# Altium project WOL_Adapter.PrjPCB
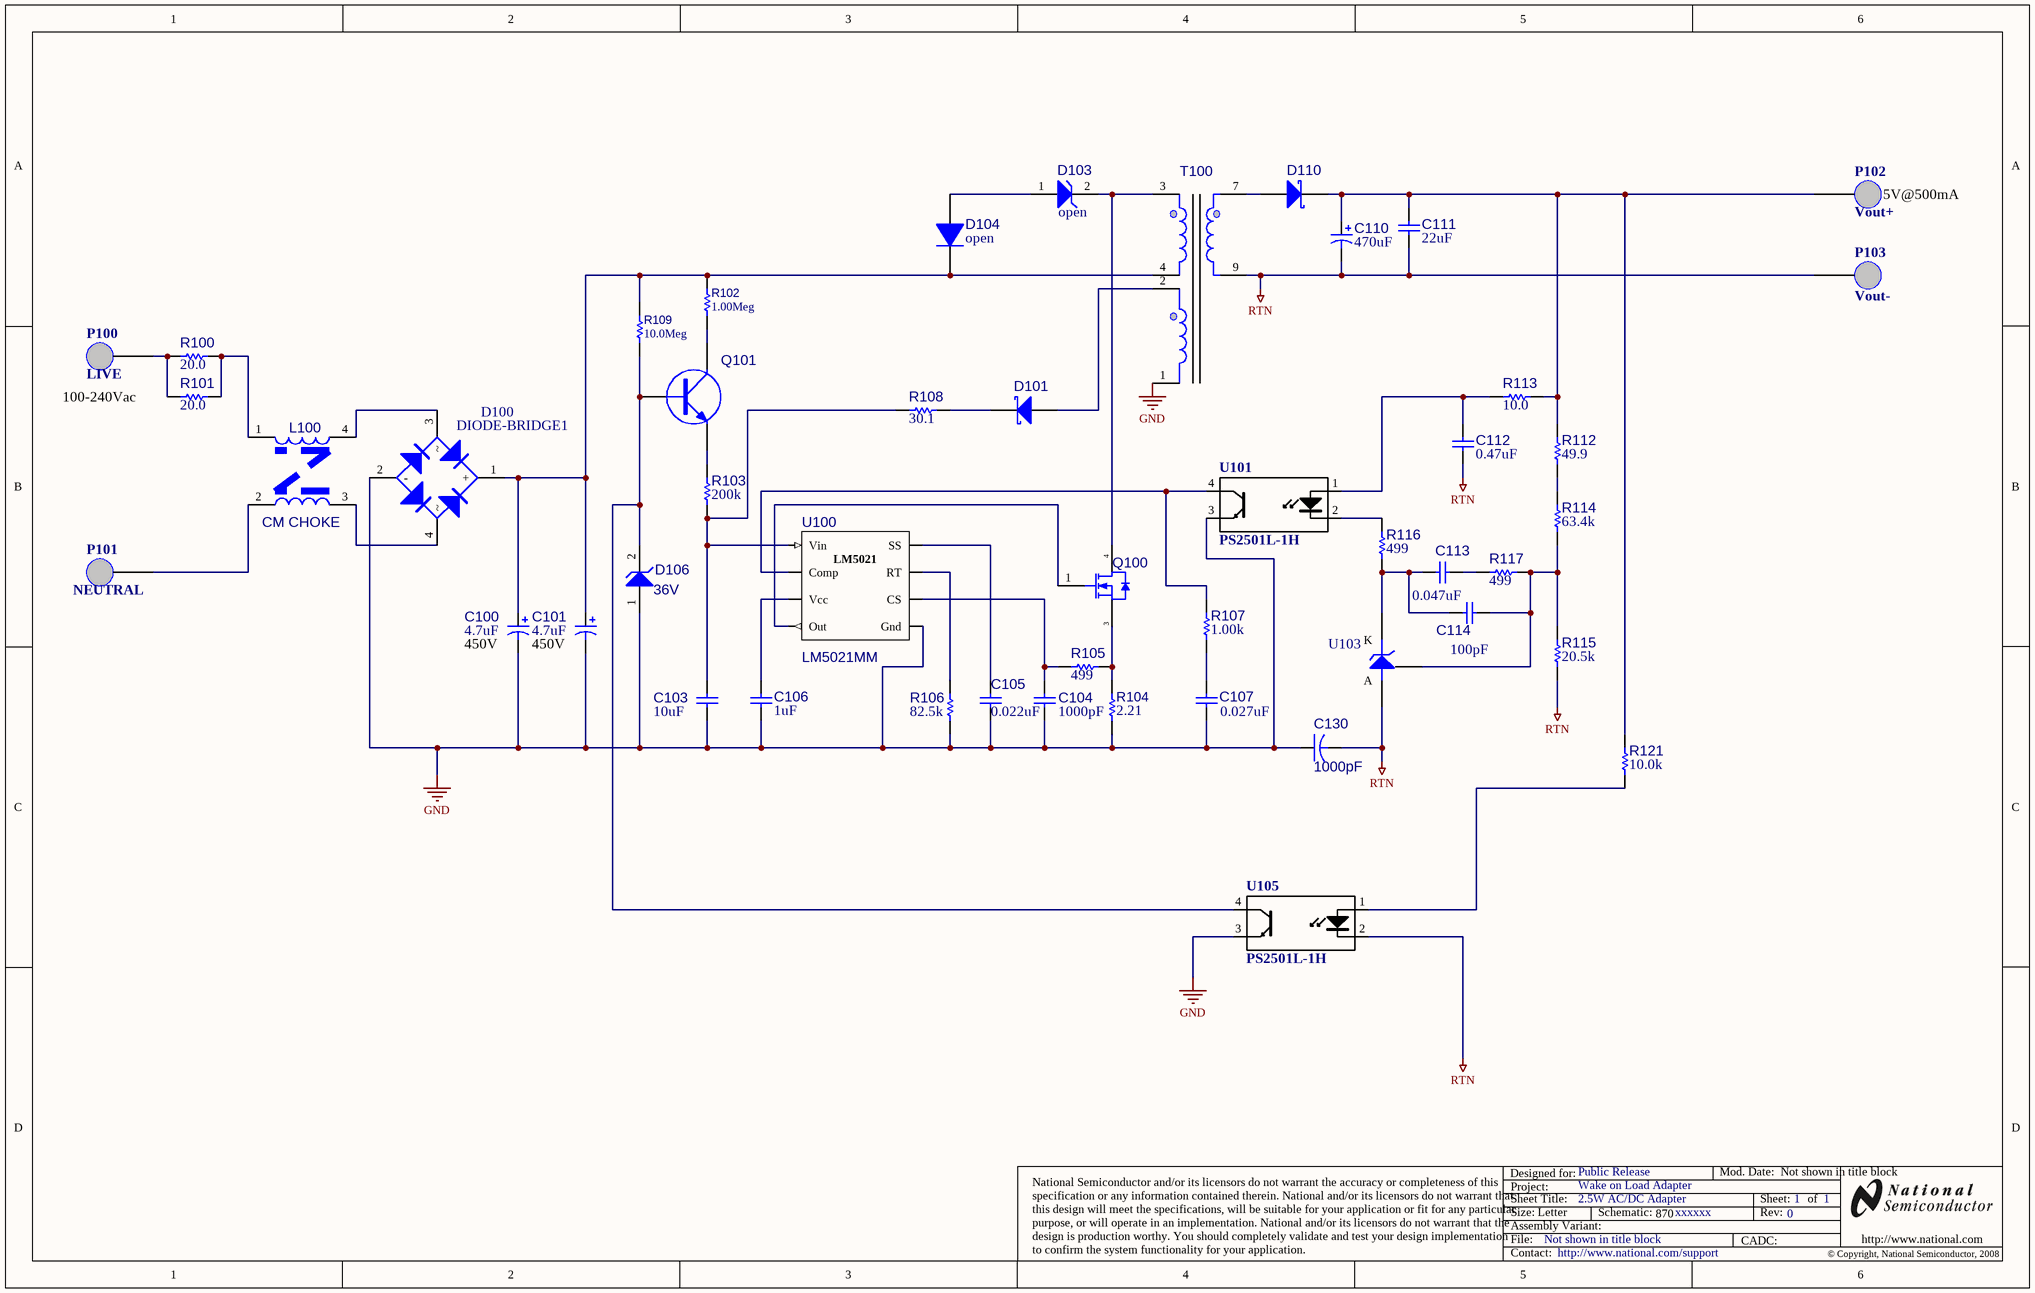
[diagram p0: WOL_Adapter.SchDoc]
PCB_MinorRev: -001; PRJ_BasePN: xxxxxx; PRJ_Customer: Public Release; PRJ_Title: Wake on Load Adapter; SCH_Rev: 0; SCH_SheetTotal: 1; TechSupport: http://www.national.com/support
1 sheet, 48 parts. Net scope: global (net labels, ports and power ports of the same name join across sheets).
Board file: WOL_Adapter.PcbDoc

## Sheet WOL_Adapter.SchDoc: 2.5W AC/DC Adapter
size B; Date: Not shown in title block; ApprovedBy: Not shown in title block; CheckedBy: Not shown in title block; Author: Not shown in title block; CompanyName: Not shown in title block; DrawnBy: Not shown in title block; Engineer: Not shown in title block; Organization: Not shown in title block; Address1: Not shown in title block; Address2: Not shown in title block; Address3: Not shown in title block; Address4: Not shown in title block; DocumentNumber: Not shown in title block; Revision: Use project parameter SCH_Rev; SheetNumber: 1; SheetTotal: Use project parameter SCH_SheetTotal; PageSetup: Record=PageOptions|CenterHorizontal=True|CenterVertical=True|PrintScale=1.09|XCorrection=1.00|YCorrection=1.00|PrintKind=0|BorderSize=5000000|LeftOffset=0|BottomOffset=0|Orientation=2|PaperLength=1000|PaperWidth=1000|Scale=100|PaperSource=15|PrintQuality=600|MediaType=1|DitherType=10|PaperKind=11x17|PrintScaleMode=1

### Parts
C100  value 4.7uF  VDC_V: 450V  [10mm th cap]  (hidden comment: UVR2W4R7MPD)
C101  value 4.7uF  VDC_V: 450V  [10mm th cap]  (hidden comment: UVR2W4R7MPD)
C103  value 10uF  [1210]  (hidden comment: C3225X7R1E106M)
C104  value 1000pF  [0805]  (hidden comment: C2012X7R1H102K)
C105  value 0.022uF  [0805]  (hidden comment: C2012X7R2A223K)
C106  value 1uF  [0805]  (hidden comment: C2012X5R1E105K)
C107  value 0.027uF  [0805]  (hidden comment: CC0805KRX7R9BB273)
C110  value 470uF  [SM_RADIAL_F]  (hidden comment: EEV-FK0J471P)
C111  value 22uF  [0805]  (hidden comment: C2012X5R0J226M)
C112  value 0.47uF  [0805]  (hidden comment: C2012X7R1E474K)
C113  value 0.047uF  [0805]  (hidden comment: GRM21BR71H473KA01L)
C114  value 100pF  [0805]  (hidden comment: GQM2195C1H101JB01D)
C130  1000pF  [1808]
D100  DIODE-BRIDGE1  [bridge]
D101  1N4148W-7-F  [SOD-123]  (value not drawn)
D103  Vaule: open  [SMA]  (hidden comment: CMZ5938B)
D104  value open  [SMA]  (hidden comment: 10MQ100NTRPBF)
D106  36V  [SMA]
D110  B2100-13  [SMB]  (value not drawn)
L100  CM CHOKE  [BU9S]
P100  LIVE  [PAD175]
P101  NEUTRAL  [PAD175]
P102  Vout+  [PAD175]
P103  Vout-  [PAD175]
Q100  SPD06N80C3  [DPAK]  (value not drawn)
Q101  (no value)  [sot-23]
R100  value 20.0  [1206]  (hidden comment: CRCW1206-20R0FRT1)
R101  value 20.0  [1206]  (hidden comment: CRCW1206-20R0FRT1)
R102  value 1.00Meg  [0805]  (hidden comment: KTR10EZPJ105)
R103  value 200k  [0805]  (hidden comment: CRCW0805200kFKEA)
R104  value 2.21  [0805]  (hidden comment: CRCW08052R21FNEA)
R105  value 499  [0805]  (hidden comment: CRCW0805499RFKEA)
R106  value 82.5k  [0805]  (hidden comment: CRCW080582k5FKEA)
R107  value 1.00k  [0805]  (hidden comment: CRCW08051k00FKEA)
R108  value 30.1  [0805]  (hidden comment: CRCW080530R1FKEA)
R109  value 10.0Meg  [0805]  (hidden comment: KTR10EZPJ106)
R112  value 49.9  [0805]  (hidden comment: CRCW080549R9FKEA)
R113  value 10.0  [0805]  (hidden comment: CRCW080510R0FKEA)
R114  value 63.4k  [0805]  (hidden comment: CRCW080563k4FKEA)
R115  value 20.5k  [0805]  (hidden comment: CRCW080520k5FKEA)
R116  value 499  [0805]  (hidden comment: CRCW0805499RFKEA)
R117  value 499  [0805]  (hidden comment: CRCW0805499RFKEA)
R121  value 10.0k  [0805]  (hidden comment: CRCW080510k0FKEA)
T100  XFMR-PA2685NL  [PA2685NL]  (value not drawn)
U100  LM5021MM  [MUA08A]
U101  PS2501L-1H  [FOD121]
U103  LMV431M5  [MF05A]  (value not drawn)
U105  PS2501L-1H  [FOD121]

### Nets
GND: C100.2(-) C101.2(-) C103.2 C104.2 C105.2 C106.2 C107.2 C130.1 D100.2(-) D106.1(A) R104.2 R106.2 T100.1 U100.5(Gnd) U101.3(E) U105.3(E)
RTN: C110.2(-) C111.2 C112.2 C130.2 P103.1 R115.2 T100.9 U103.5(A) U105.2(K)
NetC100_1: C100.1(+) C101.1(+) D100.1(+) D104.2(K) R102.1 R109.1 T100.4
NetC103_1: C103.1 R103.2 R108.2 U100.2(Vin)
NetC104_1: C104.1 R105.2 U100.6(CS)
NetC105_1: C105.1 U100.8(SS)
NetC106_1: C106.1 U100.3(Vcc)
NetC107_1: C107.1 R107.2
NetC110_1: C110.1(+) C111.1 D110.2(K) P102.1 R112.1 R113.1 R121.1
NetC112_1: C112.1 R113.2 U101.1(A)
NetC113_1: C113.1 R117.1
NetC113_2: C113.2 C114.2 R116.2 U103.3(K)
NetC114_1: C114.1 R114.2 R115.1 R117.2 U103.4(FB)
NetD100_3: D100.3 L100.4
NetD100_4: D100.4 L100.3
NetD101_1: D101.1(A) T100.2
NetD101_2: D101.2(K) R108.1
NetD103_1: D103.1(A) D104.1(A)
NetD103_2: D103.2(K) Q100.4(D) T100.3
NetD106_2: D106.2(K) Q101.1(B) R109.2 U105.4(C)
NetD110_1: D110.1(A) T100.7
NetL100_1: L100.1 R100.1 R101.1
NetL100_2: L100.2 P101.1
NetP100_1: P100.1 R100.2 R101.2
NetQ100_1: Q100.1(G) U100.4(Out)
NetQ100_3: Q100.3(S) R104.1 R105.1
NetQ101_2: Q101.2(E) R103.1
NetQ101_3: Q101.3(C) R102.2
NetR106_1: R106.1 U100.7(RT)
NetR107_1: R107.1 U100.1(Comp) U101.4(C)
NetR112_2: R112.2 R114.1
NetR116_1: R116.1 U101.2(K)
NetR121_2: R121.2 U105.1(A)

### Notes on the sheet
- (near P102) 5V@500mA
- 100-240Vac

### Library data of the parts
C100 C101 = WB_CAP_POLARIZED: Polarized Capacitor; Manufacturer: Nichicon; Polarized: Y; Voltage: V450
C103 = C3225X7R1E106M: Capacitor; Manufacturer: TDK; ESR_Ohm: 0.0027; IRMS_A: 3; Polarized: N; TaMax_C: 125; TaMin_C: -55; Tolerance_%: 20; VDC_V: 25; Cap_F: 10.0E-6; Value1: 0.0027Ohm; Value2: 25V; Dielectric: X7R
C104 = C2012X7R1H102K: Capacitor; Manufacturer: TDK; ESR_Ohm: 0; Polarized: N; TaMax_C: 125; TaMin_C: -55; Tolerance_%: 10; VDC_V: 50; Cap_F: 1.0E-9; Value1: 0Ohm; Value2: 50V; Dielectric: X7R
C105 = C2012X7R2A223K: Capacitor; Manufacturer: TDK; ESR_Ohm: 0; Polarized: N; TaMax_C: 125; TaMin_C: -55; Tolerance_%: 10; VDC_V: 100; Cap_F: 22.0E-9; Value1: 0Ohm; Value2: 100V; Dielectric: X7R
C106 = C2012X5R1E105K: Capacitor; Manufacturer: TDK; ESR_Ohm: 0; Polarized: N; TaMax_C: 125; TaMin_C: -55; Tolerance_%: 10; VDC_V: 25; Cap_F: 1.0E-6; Value1: 0Ohm; Value2: 25V; Dielectric: X5R
C107 = CC0805KRX7R9BB273: Capacitor; Manufacturer: Yageo America; ESR_Ohm: 0; Polarized: N; TaMax_C: 125; TaMin_C: -55; Tolerance_%: 10; VDC_V: 50; Cap_F: 27.0E-9; Value1: 0Ohm; Value2: 50V; Dielectric: X7R
C110 = EEV-FK0J471P: Polarized Capacitor; Manufacturer: Panasonic; ESR_Ohm: 0.16; IRMS_A: 0.6; Polarized: Y; TaMax_C: 105; TaMin_C: -55; Tolerance_%: 20; VDC_V: 6.3; Cap_F: 470.0E-6; Value1: 0.16Ohm; Value2: 6.3V; Dielectric: EEV-FK
C111 = C2012X5R0J226M: Capacitor; Manufacturer: TDK; Polarized: N; Tolerance_%: 20; VDC_V: 6.3; Cap_F: 22.0E-6; Value1: Ohm; Value2: 6.3V; Dielectric: X5R
C112 = C2012X7R1E474K: Capacitor; Manufacturer: TDK; ESR_Ohm: 0; Polarized: N; TaMax_C: 125; TaMin_C: -55; Tolerance_%: 10; VDC_V: 25; Cap_F: 470.0E-9; Value1: 0Ohm; Value2: 25V; Dielectric: X7R
C113 = GRM21BR71H473KA01L: Capacitor; Manufacturer: MuRata; ESR_Ohm: 0; Polarized: N; TaMax_C: 125; TaMin_C: -55; Tolerance_%: 10; VDC_V: 50; Cap_F: 47.0E-9; Value1: 0Ohm; Value2: 50V; Dielectric: X7R
C114 = GQM2195C1H101JB01D: Capacitor; Manufacturer: MuRata; ESR_Ohm: 0; Polarized: N; TaMax_C: 125; TaMin_C: -55; Tolerance_%: 5; VDC_V: 50; Cap_F: 100.0E-12; Value1: 0Ohm; Value2: 50V; Dielectric: C0G/NP0
C130 = CAP-1808: Capacitor Ceramic X7R; Text Field1: 1206
D100 = DIODE-BRIDGE1: Diode Bridge; Part Number: HD04 Mini Dip  Bridge Diode; Manufacture: Diodes Inc.; Voltage: 400V
D101 = 1N4148W-7-F: Schottky Diode; Manufacturer: Diodes Inc.; RJC_CperW: 0; Vf_V: 1.25; Io_A: 0.15; Vr_V: 100; TJMax_C: 150; Type: Ultrafast; Value: 1.25V; Value1: 0.15A; Value2: 100V
D103 = WB_Zener: Manufacturer: Central Semiconductor; CompType: Zener
D104 = WB_DIODE: Diode; Manufacturer: INTERNATIONAL RECT.; CompType: Zener Diode
D106 = WB_Zener: Manufacturer: Central Semiconductor; Manufacturer_PN: CMZ5938B; CompType: Zener
D110 = B2100-13: Schottky Diode; Manufacturer: Diodes Inc.; RJC_CperW: 15; Vf_V: 0.79; Io_A: 2; Vr_V: 100; TJMax_C: 150; Value: 0.79V; Value1: 2A; Value2: 100V
L100 = IND-COMMON MODE CHOKE: coil craft common mode choke; Part Number: UU9.8V-103LF; Manufacture: Gc1 Technologies
P100 P103 = PAD175: TEST POINT; Part Number: 2110-2-00-01-00-00-07-0; Manufacture: Milmax Inc.
P101 = PAD175: TEST POINT; Part Number: 2110-2-00-01-00-00-07-0; Manufacture: Milmax Inc
P102 = PAD175: TEST POINT; Part Number: 2110-2-00-01-00-00-07-0; Manufacure: Milmax Inc.
Q100 = SPD06N80C3: Manufacturer: Infineon; CompType: MOSFET; ChType: N; VdsMax_V: 800; Value1: 0.9Ohm; Rdson45_Ohm: 0.9; IdsMax_A: 6A; Value: 800V
Q101 = MMBTA42: NPN Transistor
R100 R101 = CRCW1206-20R0FRT1: Resistor; Manufacturer: Vishay-Dale; Tolerance_%: 1; VDC_V: 250; Power_W: 0.125; Res_Ohm: 20; Value_Code: 20R0; Value1: 1%; Value2: 0.125W
R102 R109 = WB_Resistor: Resistor; Manufacturer: ROHM; Tolerance_%: 5; VDC_V: 400
R103 = CRCW0805200kFKEA: Resistor; Manufacturer: Vishay-Dale; Tolerance_%: 1; VDC_V: 150; Power_W: 0.125; Res_Ohm: 200000; Value1: 1%; Value2: 0.125W
R104 = CRCW08052R21FNEA: Resistor; Manufacturer: Vishay-Dale; Tolerance_%: 1; VDC_V: 150; Power_W: 0.125; Value_Code: 2R21; Value1: 1%; Value2: 0.125W
R105 R116 R117 = CRCW0805499RFKEA: Resistor; Manufacturer: Vishay-Dale; Tolerance_%: 1; VDC_V: 150; Power_W: 0.125; Value_Code: 499R; Value1: 1%; Value2: 0.125W
R106 = CRCW080582k5FKEA: Resistor; Manufacturer: Vishay-Dale; Tolerance_%: 1; VDC_V: 150; Power_W: 0.125; Res_Ohm: 82500; Value_Code: 82k5; Value1: 1%; Value2: 0.125W
R107 = CRCW08051k00FKEA: Resistor; Manufacturer: Vishay-Dale; Tolerance_%: 1; VDC_V: 150; Power_W: 0.125; Res_Ohm: 1000; Value_Code: 1k00; Value1: 1%; Value2: 0.125W
R108 = CRCW080530R1FKEA: Resistor; Manufacturer: Vishay-Dale; Tolerance_%: 1; VDC_V: 150; Power_W: 0.125; Value_Code: 30R1; Value1: 1%; Value2: 0.125W
R112 = CRCW080549R9FKEA: Resistor; Manufacturer: Vishay-Dale; Tolerance_%: 1; VDC_V: 150; Power_W: 0.125; Value_Code: 49R9; Value1: 1%; Value2: 0.125W
R113 = CRCW080510R0FKEA: Resistor; Manufacturer: Vishay-Dale; Tolerance_%: 1; VDC_V: 150; Power_W: 0.125; Res_Ohm: 10; Value_Code: 10R0; Value1: 1%; Value2: 0.125W
R114 = CRCW080563k4FKEA: Resistor; Manufacturer: Vishay-Dale; Tolerance_%: 1; VDC_V: 150; Power_W: 0.125; Res_Ohm: 63400; Value_Code: 63k4; Value1: 1%; Value2: 0.125W
R115 = CRCW080520k5FKEA: Resistor; Manufacturer: Vishay-Dale; Tolerance_%: 1; VDC_V: 150; Power_W: 0.125; Res_Ohm: 20500; Value_Code: 20k5; Value1: 1%; Value2: 0.125W
R121 = CRCW080510k0FKEA: Resistor; Manufacturer: Vishay-Dale; Tolerance_%: 1; VDC_V: 150; Power_W: 0.125; Res_Ohm: 10000; Value_Code: 10k0; Value1: 1%; Value2: 0.125W
T100 = XFMR-PA1407: POE TRANSFORMER; Manufacture: Pulse; PA2685NL: 10Khz; DCR: (2-3) = 6.0, (7-9) = 0.22, (4-5) = 0.35
U100 = LM5021MM-1: AC-DC Current Mode PWM Controller; CompType: Switcher; Vendor: National Semiconductor; base_pn: LM5021
U101 U105 = PS2501L-1H: Full Pitch Mini-Flat Package Transistor Output  Optocoupler; PartNumber: PS2501L-1-H; Manufacturer: NEC
U103 = LMV431IM5: Low-Voltage (1.24V) Adjustable Precision Shunt Regulators; Manufacturer: National Semiconductor; Base_PN: LMV431; CompType: Voltage Reference

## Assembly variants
-100A: all parts fitted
